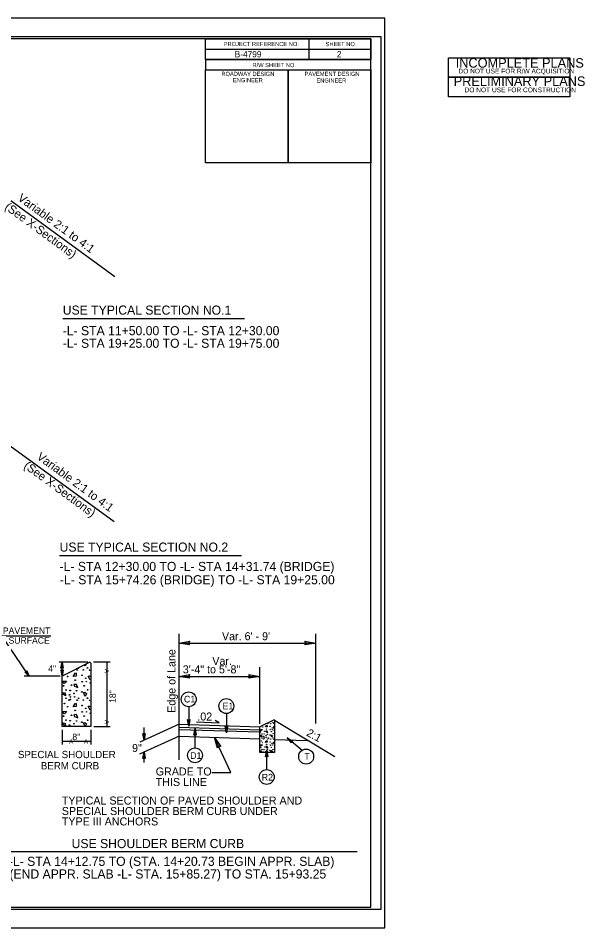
# Model space of a CAD drawing. Extents: x 573693 to 575619, y -55388 to -54288.
# Drawn here: x 574934 to 575619, y -55388 to -54288 of the extents above; entities that cross this region are included whole.
import ezdxf

# ---------------------------------------------------------------- set-up
doc = ezdxf.new("R2010")
doc.units = 0
for name, color, linetype in [('Default', 7, 'Continuous'), ('Old_Level_2', 7, 'Continuous'), ('Old_Level_23', 7, 'Continuous'), ('Old_Level_3', 7, 'Continuous'), ('Old_Level_7', 7, 'Continuous'), ('Prop Dimension', 7, 'Continuous'), ('Sheet Border Standard 30in CELL', 7, 'Continuous'), ('Sheet Cutting Line CELL', 7, 'Continuous'), ('Sheet Data Field CELL', 7, 'Continuous'), ('Sheet Plot Border Inside CELL', 7, 'Continuous'), ('Sheet Plot Border Outside CELL', 7, 'Continuous'), ('Sheet Sticker Incomplete CELL', 7, 'Continuous'), ('Sheet Sticker Preliminary CELL', 7, 'Continuous'), ('Typical ID Circle CELL', 7, 'Continuous'), ('Typical Terminator CELL', 7, 'Continuous'), ('Typical Text Grade Point CELL', 7, 'Continuous'), ('Typical Text ID Circle CELL', 7, 'Continuous')]:
    doc.layers.add(name, color=color, linetype=linetype)

msp = doc.modelspace()

# ---------------------------------------------------------------- linework, layer by layer
at = {"layer": 'Default'}
for p, q in [((575128.2, -55185.3), (575128.2, -55032.8)), ((575293.4, -55141.5), (575293.4, -55032.7)), ((575127.7, -55044), (575293.4, -55044)), ((575225.7, -55141.6), (575225.7, -55073.2)), ((575128.2, -55084.4), (575225.7, -55084.4)), ((575128.2, -55142.2), (575080.7, -55163.7)), ((575128.2, -55142.2), (575225.9, -55145.4)), ((575149.2, -55139.4), (575176.7, -55140.5)), ((575176.7, -55140.5), (575171.7, -55137.8)), ((575243.6, -55137.3), (575316.3, -55181.1)), ((575128.2, -55145.6), (575225.9, -55148.8)), ((575128.2, -55148.4), (575225.9, -55151.6)), ((575128.1, -55156.8), (575080.2, -55178.3)), ((575128.1, -55156.8), (575225.9, -55160)), ((575190.7, -55200.6), (575171, -55158.2)), ((575243.6, -55160.6), (575283, -55161.9)), ((575167.6, -55200.6), (575190.7, -55200.6))]:
    msp.add_line(p, q, dxfattribs=at)
at = {"layer": 'Old_Level_2'}
for p, q in [((574941.9, -55079.1), (574944, -55077.7)), ((574946.8, -55084.2), (574941.9, -55079.1)), ((574946.8, -55084.2), (574944, -55077.7))]:
    msp.add_line(p, q, dxfattribs=at)
for points in [[(574986.6, -55067), (574987.9, -55074.5), (574985.3, -55074.5)], [(574986.7, -55084.1), (574985.4, -55076.6), (574988, -55076.6)]]:
    msp.add_lwpolyline(points, close=True, dxfattribs=at)
msp.add_lwpolyline([(574943.1, -55078.4), (574946.7, -55084.1), (574942.5, -55078.7), (574946.7, -55084.1), (574943.6, -55078), (574946.7, -55083.9), (574943.3, -55078.3), (574946.7, -55084.1), (574942.7, -55078.6), (574946.7, -55084.1), (574942.3, -55078.9), (574946.7, -55084.1), (574942.1, -55079.1), (574946.7, -55083.9), (574942.9, -55078.5), (574946.6, -55083.9), (574943.8, -55077.8), (574946.7, -55083.9), (574943.5, -55078.1), (574946.3, -55083.5), (574943.2, -55078.3), (574946.7, -55083.9), (574943.1, -55078.3), (574946.6, -55083.9), (574942.4, -55078.9), (574946.5, -55083.7), (574942.7, -55078.7), (574946.5, -55083.7), (574943.7, -55077.9), (574946.7, -55083.9), (574944, -55077.8), (574946.6, -55083.9), (574944, -55077.8), (574946.7, -55083.9), (574945.8, -55082.1), (574946.5, -55083.7), (574943.6, -55078), (574946.5, -55083.7), (574942.1, -55079.1), (574946.5, -55083.7), (574942, -55079.1), (574946.7, -55084.1), (574942.3, -55078.9), (574946.5, -55083.7), (574942.9, -55078.5), (574946.5, -55083.7), (574942.7, -55078.6), (574946.5, -55083.7), (574943.4, -55078.2), (574946.7, -55083.9), (574943.9, -55077.8), (574946.7, -55083.9), (574942.1, -55078.9), (574946.7, -55083.9), (574942.4, -55078.7), (574946.5, -55083.7), (574942.9, -55078.5), (574946.5, -55083.9), (574943.1, -55078.3), (574946.6, -55083.9), (574943.3, -55078.2), (574946.6, -55083.9), (574943.5, -55078.1), (574946.6, -55083.9), (574943.8, -55077.9), (574946.6, -55083.9), (574943.7, -55077.9), (574946.7, -55083.9), (574943.9, -55077.8), (574946.5, -55083.9), (574942.7, -55078.5), (574946.7, -55084.1), (574943.1, -55078.4), (574946.7, -55083.9), (574942.7, -55078.7), (574946.7, -55083.9), (574942.6, -55078.7), (574946.5, -55083.7), (574942.3, -55078.9), (574946.7, -55083.9), (574942.1, -55078.9), (574945.8, -55083), (574942.1, -55079.1), (574944.7, -55081.8), (574942, -55079.1), (574944.5, -55081.4), (574942.5, -55078.7), (574944.3, -55081), (574943.3, -55078.3), (574945.6, -55082.3), (574943.3, -55078.1), (574945.2, -55081.8), (574943.3, -55078.3), (574944.9, -55081.2), (574943, -55078.4), (574944.5, -55080.8), (574942.9, -55078.5), (574945.8, -55082.4), (574943.5, -55078.1), (574945.4, -55081.4), (574943.6, -55078)], dxfattribs=at)
at = {"layer": 'Old_Level_23'}
for p, q in [((574983.1, -55066.7), (575018, -55066.7)), ((574986.7, -55084.1), (574986.7, -55066.7)), ((575024.7, -55066.8), (575044.7, -55066.8)), ((575040.8, -55066.8), (575040.8, -55145)), ((574984.3, -55084.1), (574940.9, -55084.1)), ((574986.7, -55148.9), (574986.7, -55166.9)), ((575021.3, -55148.9), (575021.3, -55166.9)), ((575025.2, -55145), (575044.7, -55145)), ((575021.3, -55163), (574986.7, -55163))]:
    msp.add_line(p, q, dxfattribs=at)
msp.add_lwpolyline([(574946.7, -55084.1), (574914, -55035.2), (574973.1, -55035.2)], dxfattribs=at)
at = {"layer": 'Old_Level_3'}
for points in [[(575021.3, -55068.4), (575020.2, -55067.3), (574986.7, -55084.1)], [(575021.3, -55068.4), (575021.3, -55145), (574986.7, -55145), (574986.7, -55084.1)], [(575243.6, -55137.3), (575243.1, -55136.8), (575225.9, -55145.4)], [(575243.6, -55137.3), (575243.6, -55176.5), (575225.9, -55176.5), (575225.9, -55145.4)]]:
    msp.add_lwpolyline(points, dxfattribs=at)
for centre, radius in [((574986.4, -55113.3), 0.381), ((575225.8, -55160.3), 0.195)]:
    msp.add_arc(centre, radius, 309.7979, 50.2021, dxfattribs=at)
at = {"layer": 'Old_Level_7'}
for p, q in [((575016.2, -55141.6), (575014.7, -55145)), ((575241, -55174.8), (575240.2, -55176.5))]:
    msp.add_line(p, q, dxfattribs=at)
for points in [[(575015.8, -55069.5), (575014.7, -55071.9), (575013.9, -55070.5)], [(575021.3, -55086.8), (575020.6, -55088.5), (575018.3, -55083.9), (575019.9, -55083.6), (575021.3, -55084.5)], [(575021.3, -55123.4), (575020.6, -55125), (575018.3, -55120.5), (575019.9, -55120.2), (575021.3, -55121.1)], [(575014.6, -55145), (575012.4, -55140.5), (575014, -55140.2), (575016.2, -55141.6)], [(575240.8, -55137.9), (575240.2, -55139.1), (575239.8, -55138.4)], [(575243.6, -55146.8), (575243.2, -55147.6), (575242.1, -55145.3), (575242.9, -55145.1), (575243.6, -55145.6)], [(575243.6, -55165.5), (575243.2, -55166.3), (575242.1, -55164), (575242.9, -55163.8), (575243.6, -55164.3)], [(575240.2, -55176.5), (575239, -55174.2), (575239.9, -55174.1), (575241, -55174.8)]]:
    msp.add_lwpolyline(points, dxfattribs=at)
for points in [[(575003.8, -55084), (575000.1, -55084.4), (575002.9, -55080.1), (575003.9, -55081.4)], [(574989.1, -55093.1), (574986.9, -55090.1), (574992, -55090.3), (574991.4, -55091.9)], [(575001.8, -55096.3), (575005.7, -55097.8), (575004, -55094.1), (575000.8, -55094.2)], [(574990.5, -55104.2), (574990.9, -55108), (574986.7, -55105.2), (574987.9, -55104.1)], [(575016.2, -55105), (575014.7, -55108.5), (575012.4, -55103.9), (575014, -55103.6)], [(575003.8, -55120.6), (575000.1, -55121), (575002.9, -55116.7), (575003.9, -55118)], [(574989.1, -55129.7), (574986.9, -55126.6), (574992, -55126.9), (574991.4, -55128.5)], [(575001.8, -55132.9), (575005.7, -55134.4), (575004, -55130.6), (575000.8, -55130.8)], [(574990.5, -55140.8), (574990.9, -55144.5), (574986.7, -55141.8), (574987.9, -55140.7)], [(575227.1, -55150), (575226, -55148.4), (575228.6, -55148.6), (575228.3, -55149.4)], [(575234.7, -55145.3), (575232.8, -55145.5), (575234.2, -55143.3), (575234.7, -55144)], [(575233.6, -55151.6), (575235.6, -55152.4), (575234.8, -55150.5), (575233.1, -55150.5)], [(575227.9, -55155.7), (575228.1, -55157.6), (575225.9, -55156.2), (575226.5, -55155.6)], [(575234.7, -55164), (575232.8, -55164.2), (575234.2, -55162), (575234.7, -55162.7)], [(575241, -55156.1), (575240.2, -55157.8), (575239, -55155.5), (575239.9, -55155.3)], [(575227.9, -55174.4), (575228.1, -55176.3), (575225.9, -55174.9), (575226.5, -55174.3)], [(575227.1, -55168.7), (575226, -55167.1), (575228.6, -55167.3), (575228.3, -55168.1)], [(575233.6, -55170.3), (575235.6, -55171.1), (575234.8, -55169.2), (575233.1, -55169.3)]]:
    msp.add_lwpolyline(points, close=True, dxfattribs=at)
for centre, radius in [((575004.9, -55076.6), 0.381), ((575012.3, -55076.4), 0.381), ((575017.4, -55074.1), 0.405), ((575019.9, -55076.8), 0.381), ((574993.3, -55084.5), 0.381), ((575010.8, -55083), 0.381), ((575015.3, -55086.6), 0.381), ((574988.4, -55095.8), 0.381), ((574998, -55094.8), 0.381), ((575002.5, -55088.9), 0.381), ((575011, -55090.8), 0.381), ((575013.4, -55095.8), 0.381), ((575016, -55090.6), 0.256), ((575020.8, -55092.3), 0.381), ((574991.5, -55100.8), 0.414), ((574995.7, -55106.7), 0.411), ((574996.5, -55101.4), 0.381), ((574996.7, -55109.2), 0.381), ((575001, -55105), 0.381), ((575001.8, -55109.1), 0.256), ((575004.1, -55101.7), 0.381), ((575010.6, -55103.2), 0.381), ((575017.5, -55100.6), 0.414), ((574989.6, -55117.3), 0.381), ((574991.4, -55110.8), 0.405), ((574993.3, -55121), 0.381), ((574995, -55113.1), 0.381), ((574996.7, -55112.3), 0.381), ((575004.9, -55113.1), 0.381), ((575006.6, -55110.8), 0.381), ((575010.8, -55119.6), 0.381), ((575012.3, -55113), 0.381), ((575017.4, -55110.7), 0.405), ((575019.9, -55113.3), 0.381), ((574998, -55131.4), 0.381), ((575002.5, -55125.5), 0.381), ((575011, -55127.3), 0.381), ((575013.4, -55132.3), 0.381), ((575015.3, -55123.1), 0.381), ((575016, -55127.2), 0.256), ((575020.8, -55128.9), 0.381), ((574988.4, -55132.4), 0.381), ((574991.5, -55137.3), 0.414), ((574995.7, -55143.3), 0.411), ((574996.5, -55138), 0.381), ((575001, -55141.6), 0.381), ((575004.1, -55138.3), 0.381), ((575010.6, -55139.7), 0.381), ((575017.5, -55137.2), 0.414), ((575235.2, -55141.5), 0.195), ((575239, -55141.4), 0.195), ((575241.6, -55140.2), 0.207), ((575242.9, -55141.6), 0.195), ((575226.8, -55151.4), 0.195), ((575228.4, -55153.9), 0.212), ((575229.3, -55145.5), 0.195), ((575231.7, -55150.9), 0.195), ((575234, -55147.8), 0.195), ((575238.2, -55144.8), 0.195), ((575238.3, -55148.8), 0.195), ((575239.6, -55151.3), 0.195), ((575240.5, -55146.6), 0.195), ((575240.9, -55148.7), 0.131), ((575241.7, -55153.8), 0.212), ((575243.4, -55149.6), 0.195), ((575227.4, -55162.4), 0.195), ((575228.3, -55159), 0.207), ((575229.3, -55164.3), 0.195), ((575230.2, -55160.2), 0.195), ((575230.5, -55156.9), 0.21), ((575230.9, -55154.2), 0.195), ((575231, -55158.2), 0.195), ((575231, -55159.8), 0.195), ((575233.2, -55156.1), 0.195), ((575233.6, -55158.1), 0.131), ((575234.8, -55154.4), 0.195), ((575235.2, -55160.2), 0.195), ((575236.1, -55159), 0.195), ((575238.1, -55155.1), 0.195), ((575238.2, -55163.5), 0.195), ((575239, -55160.1), 0.195), ((575241.6, -55159), 0.207), ((575242.9, -55160.3), 0.195), ((575226.8, -55170.1), 0.195), ((575228.4, -55172.6), 0.212), ((575230.5, -55175.6), 0.21), ((575230.9, -55173), 0.195), ((575231.7, -55169.6), 0.195), ((575233.2, -55174.8), 0.195), ((575234, -55166.6), 0.195), ((575234.8, -55173.1), 0.195), ((575238.1, -55173.8), 0.195), ((575238.3, -55167.5), 0.195), ((575239.6, -55170), 0.195), ((575240.5, -55165.3), 0.195), ((575240.9, -55167.4), 0.131), ((575241.7, -55172.5), 0.212), ((575243.4, -55168.3), 0.195)]:
    msp.add_circle(centre, radius, dxfattribs=at)
for centre, radius, start, end in [((575006.6, -55074.2), 0.381, 193.5972, 39.5125), ((575021.7, -55070), 0.411, 157.2508, 202.7492), ((575021.7, -55106.5), 0.411, 157.2508, 202.7492), ((575021.7, -55143.1), 0.411, 157.2508, 202.7492), ((575236.1, -55140.3), 0.195, 193.5972, 39.5125), ((575243.8, -55138.1), 0.21, 157.2508, 202.7492), ((575233.1, -55157.4), 0.0841, 157.2508, 202.7492), ((575243.8, -55156.8), 0.21, 157.2508, 202.7492), ((575243.8, -55175.6), 0.21, 157.2508, 202.7492)]:
    msp.add_arc(centre, radius, start, end, dxfattribs=at)
at = {"layer": 'Prop Dimension'}
for p, q in [((574916, -54502.5), (575050.3, -54600.8)), ((574987.5, -54651.5), (575207.4, -54651.5)), ((574915.2, -54799), (575049.5, -54897.2)), ((574983.7, -54938.1), (575203.6, -54938.1)), ((574891.8, -55296), (575343.6, -55296))]:
    msp.add_line(p, q, dxfattribs=at)
at = {"layer": 'Sheet Border Standard 30in CELL'}
for p, q in [((575285, -54313.4), (575285, -54338.4)), ((575159.9, -54325.9), (575360, -54325.9)), ((575159.9, -54338.4), (575360, -54338.4)), ((575159.9, -54338.4), (575159.9, -54350.9)), ((575159.9, -54338.4), (575360, -54338.4)), ((575260, -54350.9), (575260, -54463.4))]:
    msp.add_line(p, q, dxfattribs=at)
for points in [[(575360, -54313.4), (573860, -54313.4), (573860, -55363.4), (575360, -55363.4)], [(575159.9, -54313.4), (575360, -54313.4), (575360, -54338.4), (575159.9, -54338.4)], [(575159.9, -54350.9), (575260, -54350.9), (575260, -54463.4), (575159.9, -54463.4)], [(575260, -54350.9), (575360, -54350.9), (575360, -54463.4), (575260, -54463.4)]]:
    msp.add_lwpolyline(points, close=True, dxfattribs=at)
at = {"layer": 'Sheet Cutting Line CELL'}
for p, q in [((575377, -54288.4), (573693, -54288.4)), ((573693, -55388.4), (575377, -55388.4))]:
    msp.add_line(p, q, dxfattribs=at)
at = {"layer": 'Sheet Plot Border Inside CELL'}
msp.add_lwpolyline([(575372.5, -54310.8), (573706, -54310.8), (573706, -55365.9), (575372.5, -55365.9)], close=True, dxfattribs=at)
at = {"layer": 'Sheet Plot Border Outside CELL'}
msp.add_lwpolyline([(575377, -54288.4), (573693, -54288.4), (573693, -55388.4), (575377, -55388.4)], close=True, dxfattribs=at)
at = {"layer": 'Sheet Sticker Incomplete CELL'}
msp.add_lwpolyline([(575453.7, -54359.9), (575453.7, -54336.4), (575600.7, -54336.4), (575600.7, -54359.9)], close=True, dxfattribs=at)
at = {"layer": 'Sheet Sticker Preliminary CELL'}
msp.add_lwpolyline([(575453.7, -54383.4), (575453.7, -54359.9), (575600.7, -54359.9), (575600.7, -54383.4)], close=True, dxfattribs=at)
at = {"layer": 'Typical ID Circle CELL'}
for p, q in [((575139.8, -55121.1), (575139.8, -55144.4)), ((575185.3, -55129.4), (575185.3, -55152.7)), ((575085.9, -55161.3), (575085.9, -55146.1)), ((575147.4, -55170.8), (575147.4, -55147.5)), ((575276.8, -55173.8), (575258.7, -55158.6)), ((575085.9, -55188.5), (575085.9, -55175.8)), ((575234.1, -55197), (575234.1, -55173.7))]:
    msp.add_line(p, q, dxfattribs=at)
for centre in [(575139.8, -55112.1), (575185.3, -55120.3), (575147.4, -55179.8), (575281.8, -55181.3), (575234.1, -55206)]:
    msp.add_circle(centre, 9.02, dxfattribs=at)
at = {"layer": 'Typical Terminator CELL'}
for points in [[(575140.9, -55046.2), (575127.7, -55044), (575141, -55041.6), (575139.3, -55044)], [(575280.2, -55041.7), (575293.4, -55044), (575280.1, -55046.3), (575281.8, -55044)], [(575140.9, -55086.7), (575127.7, -55084.4), (575141, -55082.1), (575139.3, -55084.4)], [(575212.5, -55082.1), (575225.7, -55084.4), (575212.4, -55086.7), (575214.1, -55084.4)], [(575141.1, -55136.5), (575139.8, -55144.4), (575138.4, -55136.5), (575139.8, -55137.5)], [(575087.3, -55153.4), (575085.9, -55161.3), (575084.5, -55153.4), (575085.9, -55154.4)], [(575146, -55155.4), (575147.4, -55147.5), (575148.8, -55155.4), (575147.4, -55154.4)], [(575186.7, -55144.8), (575185.3, -55152.7), (575183.9, -55144.7), (575185.3, -55145.7)], [(575174.6, -55171.1), (575171, -55158.2), (575178.8, -55169.2), (575176, -55168.7)], [(575264, -55164.6), (575258.7, -55158.6), (575265.8, -55162.5), (575264.1, -55162.9)], [(575084.5, -55183.5), (575085.9, -55175.6), (575087.3, -55183.6), (575085.9, -55182.6)], [(575232.7, -55181.6), (575234.1, -55173.7), (575235.5, -55181.7), (575234.1, -55180.6)]]:
    msp.add_lwpolyline(points, close=True, dxfattribs=at)

# ---------------------------------------------------------------- texts
at = {"layer": 'Default'}
for s, height, p in [("Var. 6' - 9'", 9.677, (575180, -55040.6)), ('Var.', 9.68, (575168.3, -55070.6)), ('3\'-4" to 5\'-8"', 9.677, (575132.6, -55080.7)), ('.02', 9.68, (575150.2, -55137.7)), ('9"', 9.68, (575071.3, -55175.8)), ('GRADE TO ', 9.68, (575099.9, -55204.2)), ('THIS LINE', 9.68, (575099.9, -55216.9)), ('TYPICAL SECTION OF PAVED SHOULDER AND ', 9.677, (574986.4, -55239.3)), ('SPECIAL SHOULDER BERM CURB UNDER ', 9.677, (574986.4, -55252)), ('TYPE III ANCHORS', 9.677, (574986.4, -55264.6))]:
    msp.add_text(s, height=height, dxfattribs=at).set_placement(p)
for s, height, rotation, p in [('Edge of Lane', 9.677, 90, (575123.8, -55128.4)), ('2:1', 9.68, 331.591, (575281.3, -55155.6))]:
    msp.add_text(s, height=height, rotation=rotation, dxfattribs=at).set_placement(p)
at = {"layer": 'Old_Level_23'}
for s, height, p in [('PAVEMENT', 7.81, (574915.1, -55033)), ('SURFACE', 7.81, (574921.9, -55044.8)), ('4"', 7.77, (574969.9, -55078.7)), ('8"', 7.79, (574999.1, -55161.4)), ('A', 5.17, (574995.4, -55165.6)), ('A', 5.17, (575013.3, -55165.7)), ('SPECIAL SHOULDER', 8.789, (574933.3, -55183.2)), ('BERM CURB', 8.79, (574961, -55196.8))]:
    msp.add_text(s, height=height, dxfattribs=at).set_placement(p)
for s, height, rotation, p in [('A', 5.17, 270, (575038.3, -55075.4)), ('18"', 7.79, 90, (575051.6, -55116.4)), ('A', 5.17, 270, (575038.1, -55137.1))]:
    msp.add_text(s, height=height, rotation=rotation, dxfattribs=at).set_placement(p)
at = {"layer": 'Sheet Border Standard 30in CELL'}
for s, p in [('PROJECT REFERENCE NO.', (575182.1, -54322.1)), ('SHEET NO.', (575305.3, -54322.2)), ('R/W SHEET NO.', (575216.9, -54347.6)), ('ROADWAY DESIGN', (575179.3, -54358.2)), ('ENGINEER', (575193.3, -54365.8)), ('PAVEMENT DESIGN', (575279.9, -54358.2)), ('ENGINEER', (575294.2, -54366.2))]:
    msp.add_text(s, height=5, dxfattribs=at).set_placement(p)
at = {"layer": 'Sheet Data Field CELL'}
for s, p in [('B-4799   ', (575195.4, -54335.7)), ('2', (575319, -54335.6))]:
    msp.add_text(s, height=7.5, dxfattribs=at).set_placement(p)
at = {"layer": 'Sheet Sticker Incomplete CELL'}
for s, height, p in [('INCOMPLETE PLANS', 11.52, (575462.6, -54348.2)), ('DO NOT USE FOR R/W ACQUISITION', 5.76, (575465.9, -54355.2))]:
    msp.add_text(s, height=height, dxfattribs=at).set_placement(p)
at = {"layer": 'Sheet Sticker Preliminary CELL'}
for s, height, p in [('PRELIMINARY PLANS', 11.52, (575460.2, -54370.3)), ('DO NOT USE FOR CONSTRUCTION', 5.76, (575473.3, -54378))]:
    msp.add_text(s, height=height, dxfattribs=at).set_placement(p)
at = {"layer": 'Typical Text Grade Point CELL'}
for s, p in [('Variable 2:1 to 4:1', (574932.2, -54507.8)), ('(See X-Sections)', (574916.4, -54518.6)), ('Variable 2:1 to 4:1', (574955.2, -54820.7)), ('(See X-Sections)', (574939.5, -54831.6))]:
    msp.add_text(s, height=10.179, rotation=323.7917, dxfattribs=at).set_placement(p)
for s, p in [('USE TYPICAL SECTION NO.1', (574987.5, -54646.9)), ('-L- STA 11+50.00 TO -L- STA 12+30.00', (574987.5, -54671.8)), ('-L- STA 19+25.00 TO -L- STA 19+75.00', (574987.5, -54687)), ('USE TYPICAL SECTION NO.2', (574983.7, -54933.5)), ('-L- STA 12+30.00 TO -L- STA 14+31.74 (BRIDGE)', (574983.7, -54956.9)), ('-L- STA 15+74.26 (BRIDGE) TO -L- STA 19+25.00', (574984.1, -54973)), ('USE SHOULDER BERM CURB', (574998.2, -55292)), ('RT -L- STA 14+12.75 TO (STA. 14+20.73 BEGIN APPR. SLAB)', (574898.6, -55313.5)), ('RT (END APPR. SLAB -L- STA. 15+85.27) TO STA. 15+93.25', (574899.3, -55328.8))]:
    msp.add_text(s, height=11.011, dxfattribs=at).set_placement(p)
at = {"layer": 'Typical Text ID Circle CELL'}
for s, p in [('C1', (575134, -55115.9)), ('E1', (575180.6, -55124.2)), ('D1', (575141.5, -55184.1)), ('R2', (575228, -55210.3))]:
    msp.add_text(s, height=8.07, dxfattribs=at).set_placement(p)
msp.add_text('T ', height=8.07, rotation=0.016, dxfattribs=at).set_placement((575279.6, -55184.9))

doc.saveas('drawing.dxf')
